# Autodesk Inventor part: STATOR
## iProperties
Created: 2011-01
Part Number: STATOR
Document SubType Name: Modeling
Designer: eric
Density: 1 g/cm^3
Mass: 31.5748 g
Surface Area: 61.5262 cm^2
Volume: 31.5748 cm^3
Author: eric
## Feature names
1. Base1
